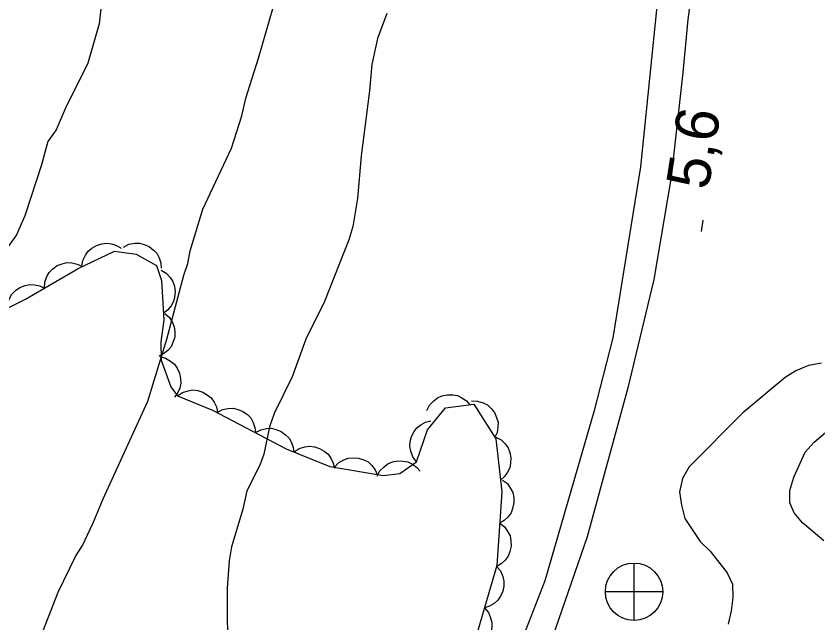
# Model space of a CAD drawing. Extents: x 282461 to 284471, y 5554090 to 5557646.
# Drawn here: x 283508.4 to 283564.3, y 5554840.5 to 5554882.8 of the extents above; entities that cross this region are included whole.
import ezdxf

# ---------------------------------------------------------------- set-up
doc = ezdxf.new("R2010")
doc.units = 0
for name, color, linetype in [('Niveau 1', 7, 'Continuous'), ('Niveau 19', 7, 'Continuous'), ('Niveau 2', 7, 'Continuous'), ('Niveau 3', 7, 'Continuous'), ('Niveau 34', 7, 'Continuous'), ('Niveau 44', 7, 'Continuous')]:
    doc.layers.add(name, color=color, linetype=linetype)

msp = doc.modelspace()

# ---------------------------------------------------------------- linework, layer by layer
at = {"layer": 'Niveau 1'}
for points in [[(283534.26, 5554882.98), (283533.59, 5554881.23), (283533.2, 5554879.43), (283533.05, 5554877.58), (283532.46, 5554873.05), (283532.2, 5554870.09), (283531.88, 5554868.12), (283531.6, 5554867.19), (283529.91, 5554862.89), (283528.6, 5554860.27), (283527.64, 5554857.65), (283526.4, 5554855.09), (283526.06, 5554854.16), (283525.67, 5554852.25), (283525.39, 5554851.49), (283524.48, 5554849.69), (283524.21, 5554848.41), (283523.42, 5554845.8), (283523.26, 5554844.81), (283523.11, 5554842.9), (283523.17, 5554832.58)], [(283564.58, 5554858.61), (283563.66, 5554858.43), (283562.79, 5554858.07), (283562.04, 5554857.6), (283559.1, 5554855.14), (283555.34, 5554851.37), (283554.88, 5554850.55), (283554.67, 5554849.62), (283554.8, 5554848.69), (283555.04, 5554847.77), (283556.11, 5554846.16), (283556.82, 5554845.48), (283558, 5554843.99), (283558.37, 5554843.18), (283558.38, 5554842.26), (283558.28, 5554841.33), (283558.06, 5554840.39)], [(283564.73, 5554846.21), (283563.26, 5554847.47), (283562.67, 5554848.16), (283562.37, 5554848.86), (283562.36, 5554849.73), (283562.64, 5554850.65), (283563.44, 5554852.4), (283564.07, 5554853.1), (283565.5, 5554854.33)]]:
    msp.add_lwpolyline(points, dxfattribs=at)
at = {"layer": 'Niveau 19'}
for points in [[(283553.73, 5554889.88), (283551.94, 5554872.28), (283550.03, 5554860.36), (283548.7, 5554855.2), (283545.28, 5554843.42), (283543.65, 5554839.23), (283542.53, 5554835.81), (283541.08, 5554830.64), (283539.86, 5554825.47), (283537.91, 5554817.81), (283537.26, 5554814.04), (283537.21, 5554813)], [(283555.84, 5554886.97), (283555.25, 5554882.56), (283554.91, 5554878.86), (283554.09, 5554871.57), (283552.89, 5554864.43), (283551.06, 5554856.89), (283548.22, 5554846.5), (283546.01, 5554840.09), (283544.21, 5554834.51), (283542.46, 5554828.51), (283539.74, 5554818), (283539.16, 5554813.02)]]:
    msp.add_lwpolyline(points, dxfattribs=at)
at = {"layer": 'Niveau 2'}
for points in [[(283524.14, 5554875.85), (283524.41, 5554877.07), (283525.31, 5554879.87), (283526.32, 5554883.41), (283527.73, 5554886.73), (283529.66, 5554890.75), (283530, 5554891.68), (283530.89, 5554894.94), (283531.48, 5554899.64), (283531.86, 5554901.32), (283533.32, 5554906.44), (283533.6, 5554907.14), (283533.65, 5554907.72), (283533.99, 5554908.88), (283534.94, 5554911.56), (283536.19, 5554914.12), (283537.61, 5554917.38), (283540.57, 5554927.56), (283540.79, 5554929.13), (283540.53, 5554931.51)], [(283514.6, 5554886.03), (283514.18, 5554882.26), (283513.4, 5554879.53), (283511.81, 5554876.33), (283511.19, 5554874.87), (283510.61, 5554874.05), (283510.17, 5554872.43), (283508.99, 5554868.88), (283508.42, 5554867.54), (283505.62, 5554863.69)], [(283507.79, 5554832.28), (283509.35, 5554837.57), (283511.33, 5554842.63), (283512.52, 5554845.13), (283513.03, 5554845.89), (283513.77, 5554847.47), (283514.45, 5554849.15), (283517.57, 5554855.96), (283518.91, 5554860.27), (283520.08, 5554864.74), (283520.36, 5554865.56), (283520.53, 5554866.43), (283521.42, 5554869.34), (283523.41, 5554873.59), (283524.14, 5554875.85)]]:
    msp.add_lwpolyline(points, dxfattribs=at)
at = {"layer": 'Niveau 3'}
msp.add_line((283556.2, 5554867.77), (283556.32, 5554868.56), dxfattribs=at)
at = {"layer": 'Niveau 34'}
for p, q in [((283551.49, 5554844.65), (283551.49, 5554840.65)), ((283553.49, 5554842.65), (283549.49, 5554842.65))]:
    msp.add_line(p, q, dxfattribs=at)
msp.add_circle((283551.497, 5554842.662), 2, dxfattribs=at)
at = {"layer": 'Niveau 44'}
for points in [[(283512.98, 5554865.34), (283513.05, 5554865.75), (283513.23, 5554866.12), (283513.41, 5554866.4), (283513.68, 5554866.62), (283514, 5554866.81), (283514.37, 5554866.92), (283514.69, 5554866.97), (283515.05, 5554866.92), (283515.4, 5554866.81), (283515.71, 5554866.62)], [(283515.88, 5554866.7), (283516.25, 5554866.89), (283516.66, 5554866.96), (283516.99, 5554866.97), (283517.33, 5554866.88), (283517.67, 5554866.73), (283517.97, 5554866.49), (283518.2, 5554866.26), (283518.36, 5554865.94), (283518.48, 5554865.59), (283518.51, 5554865.23)], [(283506.62, 5554861.86), (283509.04, 5554863.06), (283512.72, 5554865.21), (283515.26, 5554866.41), (283516.77, 5554866.2), (283518.18, 5554865.41), (283518.54, 5554864.37), (283518.7, 5554861.59), (283518.49, 5554860.08), (283518.51, 5554858.8), (283519.18, 5554856.94), (283519.64, 5554856.33)], [(283510.37, 5554863.84), (283510.39, 5554864.25), (283510.54, 5554864.64), (283510.7, 5554864.93), (283510.95, 5554865.18), (283511.25, 5554865.4), (283511.61, 5554865.53), (283511.93, 5554865.61), (283512.28, 5554865.59), (283512.65, 5554865.51), (283512.97, 5554865.36)], [(283518.5, 5554865.09), (283518.86, 5554864.88), (283519.13, 5554864.57), (283519.32, 5554864.3), (283519.43, 5554863.96), (283519.49, 5554863.6), (283519.44, 5554863.21), (283519.37, 5554862.89), (283519.2, 5554862.59), (283518.96, 5554862.3), (283518.67, 5554862.08)], [(283507.76, 5554862.31), (283507.79, 5554862.73), (283507.93, 5554863.12), (283508.09, 5554863.41), (283508.34, 5554863.66), (283508.64, 5554863.87), (283509.01, 5554864.01), (283509.32, 5554864.09), (283509.68, 5554864.07), (283510.04, 5554863.99), (283510.37, 5554863.84)], [(283518.77, 5554862.07), (283519.08, 5554861.79), (283519.29, 5554861.44), (283519.42, 5554861.14), (283519.47, 5554860.79), (283519.45, 5554860.42), (283519.33, 5554860.05), (283519.2, 5554859.75), (283518.97, 5554859.48), (283518.68, 5554859.25), (283518.35, 5554859.09)], [(283518.42, 5554859.06), (283518.82, 5554858.96), (283519.17, 5554858.74), (283519.43, 5554858.54), (283519.63, 5554858.25), (283519.79, 5554857.91), (283519.86, 5554857.53), (283519.88, 5554857.2), (283519.8, 5554856.86), (283519.65, 5554856.51), (283519.44, 5554856.22)], [(283519.64, 5554856.33), (283519.99, 5554856.56), (283520.38, 5554856.68), (283520.71, 5554856.74), (283521.06, 5554856.69), (283521.41, 5554856.58), (283521.74, 5554856.38), (283522, 5554856.18), (283522.2, 5554855.89), (283522.36, 5554855.55), (283522.44, 5554855.19)], [(283519.64, 5554856.33), (283522.1, 5554855.33), (283527.24, 5554852.63), (283530.28, 5554851.4), (283534.01, 5554850.77), (283535.17, 5554850.9), (283536.31, 5554851.73), (283537.09, 5554853.95), (283538.35, 5554855.48), (283540.31, 5554855.74), (283541.86, 5554853.33), (283542.27, 5554849.63), (283541.93, 5554844.5), (283540.17, 5554838.45)], [(283537.05, 5554855.31), (283537.24, 5554855.68), (283537.52, 5554855.98), (283537.78, 5554856.19), (283538.1, 5554856.32), (283538.47, 5554856.4), (283538.85, 5554856.39), (283539.18, 5554856.34), (283539.49, 5554856.19), (283539.8, 5554855.97), (283540.04, 5554855.7)], [(283540.16, 5554855.97), (283540.58, 5554855.96), (283540.97, 5554855.83), (283541.27, 5554855.69), (283541.53, 5554855.45), (283541.76, 5554855.15), (283541.91, 5554854.8), (283542.01, 5554854.49), (283542, 5554854.13), (283541.94, 5554853.76), (283541.79, 5554853.43)], [(283522.42, 5554855.16), (283522.79, 5554855.36), (283523.19, 5554855.44), (283523.52, 5554855.46), (283523.87, 5554855.38), (283524.21, 5554855.24), (283524.52, 5554855.01), (283524.76, 5554854.78), (283524.93, 5554854.47), (283525.05, 5554854.12), (283525.09, 5554853.76)], [(283536.31, 5554851.73), (283536.06, 5554852.07), (283535.92, 5554852.46), (283535.85, 5554852.78), (283535.88, 5554853.13), (283535.97, 5554853.49), (283536.16, 5554853.83), (283536.35, 5554854.1), (283536.63, 5554854.31), (283536.96, 5554854.49), (283537.31, 5554854.58)], [(283525.09, 5554853.76), (283525.46, 5554853.96), (283525.86, 5554854.04), (283526.19, 5554854.06), (283526.54, 5554853.98), (283526.88, 5554853.84), (283527.19, 5554853.6), (283527.43, 5554853.38), (283527.6, 5554853.07), (283527.72, 5554852.71), (283527.76, 5554852.36)], [(283541.85, 5554853.45), (283542.22, 5554853.25), (283542.51, 5554852.97), (283542.71, 5554852.7), (283542.84, 5554852.37), (283542.91, 5554852.01), (283542.89, 5554851.62), (283542.84, 5554851.3), (283542.68, 5554850.99), (283542.45, 5554850.69), (283542.18, 5554850.45)], [(283527.79, 5554852.41), (283528.14, 5554852.64), (283528.53, 5554852.76), (283528.86, 5554852.82), (283529.21, 5554852.77), (283529.56, 5554852.66), (283529.89, 5554852.46), (283530.15, 5554852.26), (283530.35, 5554851.97), (283530.51, 5554851.63), (283530.59, 5554851.28)], [(283530.6, 5554851.35), (283530.89, 5554851.65), (283531.25, 5554851.85), (283531.56, 5554851.97), (283531.91, 5554852.01), (283532.28, 5554851.98), (283532.65, 5554851.85), (283532.94, 5554851.71), (283533.2, 5554851.47), (283533.43, 5554851.17), (283533.58, 5554850.84)], [(283533.58, 5554850.72), (283533.77, 5554851.09), (283534.06, 5554851.38), (283534.32, 5554851.59), (283534.65, 5554851.72), (283535.02, 5554851.79), (283535.4, 5554851.77), (283535.72, 5554851.72), (283536.04, 5554851.55), (283536.34, 5554851.33), (283536.58, 5554851.06)], [(283542.32, 5554850.45), (283542.66, 5554850.2), (283542.89, 5554849.86), (283543.05, 5554849.57), (283543.11, 5554849.22), (283543.12, 5554848.85), (283543.03, 5554848.47), (283542.92, 5554848.16), (283542.71, 5554847.88), (283542.44, 5554847.63), (283542.13, 5554847.44)], [(283542.13, 5554847.44), (283542.46, 5554847.18), (283542.69, 5554846.85), (283542.85, 5554846.56), (283542.91, 5554846.21), (283542.92, 5554845.84), (283542.83, 5554845.46), (283542.72, 5554845.15), (283542.51, 5554844.87), (283542.24, 5554844.61), (283541.93, 5554844.43)], [(283541.91, 5554844.43), (283542.18, 5554844.11), (283542.34, 5554843.73), (283542.42, 5554843.41), (283542.42, 5554843.06), (283542.34, 5554842.69), (283542.18, 5554842.35), (283542, 5554842.07), (283541.73, 5554841.84), (283541.41, 5554841.65), (283541.07, 5554841.54)], [(283541.07, 5554841.54), (283541.34, 5554841.21), (283541.49, 5554840.84), (283541.58, 5554840.52), (283541.57, 5554840.16), (283541.5, 5554839.8), (283541.33, 5554839.45), (283541.16, 5554839.17), (283540.89, 5554838.94), (283540.57, 5554838.75), (283540.23, 5554838.64)]]:
    msp.add_lwpolyline(points, dxfattribs=at)

# ---------------------------------------------------------------- texts
at = {"layer": 'Niveau 3'}
msp.add_text('5,6  ', height=3, rotation=81.0957, dxfattribs=at).set_placement((283556.68, 5554870.61))

doc.saveas('drawing.dxf')
